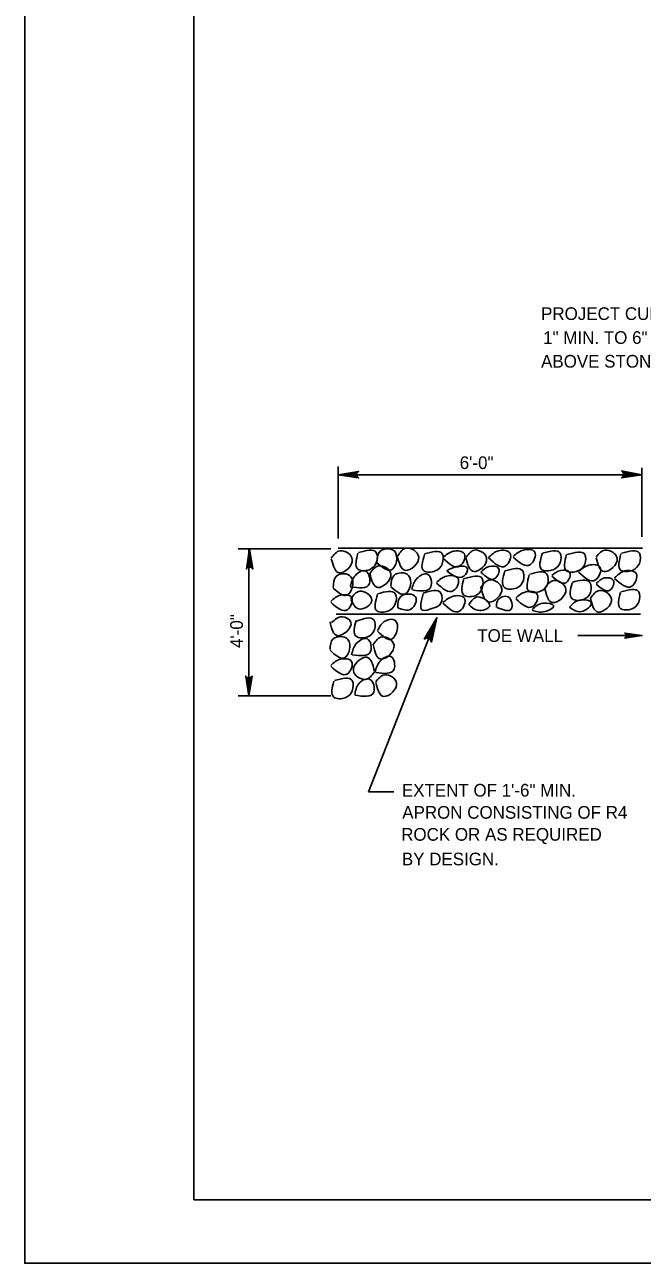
# Model space of a CAD drawing. Extents: x 639011 to 639866, y 298840 to 300028.
# Drawn here: x 639011.3 to 639157.4, y 298839.8 to 299133.1 of the extents above; entities that cross this region are included whole.
import ezdxf

# ---------------------------------------------------------------- set-up
doc = ezdxf.new("R2010")
doc.units = 0
doc.layers.add('2', color=7, linetype='Continuous')
doc.layers.add('PLT-BNDY', color=7, linetype='Continuous')

msp = doc.modelspace()

# ---------------------------------------------------------------- linework, layer by layer
at = {"layer": '2'}
for p, q in [((639051.26, 298854.83), (639051.26, 299418.83)), ((639085.44, 299011.4), (639085.44, 299028.5)), ((639157.29, 299011.85), (639157.29, 299028.2)), ((639085.44, 299026.55), (639157.29, 299026.55)), ((639061.74, 299009), (639083.64, 299009)), ((639064.29, 298974.2), (639064.29, 299008.85)), ((639085.44, 299009.15), (639157.44, 299009.15)), ((639084.98, 298993.53), (639156.98, 298993.53)), ((639108.79, 298992.68), (639092.56, 298951.49)), ((639142.14, 298988.45), (639157.29, 298988.45)), ((639061.74, 298974.2), (639083.64, 298974.2)), ((639092.56, 298951.49), (639098.56, 298951.49)), ((639837.26, 298854.83), (639051.26, 298854.83))]:
    msp.add_line(p, q, dxfattribs=at)
for points in [[(639089.94, 299026.1), (639089.79, 299026.4), (639085.44, 299026.55), (639089.94, 299026.1), (639090.24, 299025.8), (639085.44, 299026.55), (639089.79, 299026.85), (639089.94, 299027.15), (639085.44, 299026.55), (639090.24, 299027.3), (639089.94, 299027.15)], [(639152.79, 299027.15), (639152.94, 299026.85), (639157.29, 299026.55), (639152.79, 299027.15), (639152.49, 299027.45), (639157.29, 299026.55), (639152.94, 299026.4), (639152.79, 299026.1), (639157.29, 299026.55), (639152.49, 299025.8), (639152.79, 299026.1)], [(639063.84, 299004.5), (639064.14, 299004.65), (639064.44, 299009), (639063.84, 299004.5), (639063.69, 299004.2), (639064.44, 299009), (639064.59, 299004.65), (639065.04, 299004.5), (639064.44, 299009), (639065.19, 299004.2), (639065.04, 299004.5)], [(639106.11, 298987.78), (639106.56, 298987.83), (639108.79, 298992.68), (639106.11, 298987.78), (639105.78, 298987.61), (639108.79, 298992.68), (639107.08, 298987.63), (639107.38, 298987.3), (639108.79, 298992.68), (639107.51, 298986.92), (639107.38, 298987.3)], [(639153.39, 298988.9), (639153.54, 298988.6), (639157.29, 298988.45), (639153.39, 298988.9), (639153.24, 298989.05), (639157.29, 298988.45), (639153.54, 298988.3), (639153.39, 298988), (639157.29, 298988.45), (639153.24, 298987.85), (639153.39, 298988)], [(639064.89, 298978.7), (639064.44, 298978.4), (639064.29, 298974.2), (639064.89, 298978.7), (639065.04, 298978.85), (639064.29, 298974.2), (639063.99, 298978.4), (639063.69, 298978.7), (639064.29, 298974.2), (639063.54, 298978.85), (639063.69, 298978.7)]]:
    msp.add_lwpolyline(points, dxfattribs=at)
for points in [[(639083.79, 299006.75), (639085.89, 299008.55), (639088.74, 299006.45), (639085.74, 299003.3), (639083.79, 299006.6)], [(639090.24, 299008.1), (639094.44, 299008.1), (639094.44, 299005.7), (639092.79, 299004.05), (639090.09, 299004.2), (639090.09, 299007.95)], [(639094.59, 299005.85), (639095.34, 299008.4), (639098.79, 299008.4), (639098.04, 299004.05), (639094.59, 299005.7)], [(639099.54, 299007.35), (639101.49, 299009.15), (639104.49, 299007.05), (639101.34, 299003.9), (639099.39, 299007.35)], [(639105.84, 299007.8), (639110.04, 299007.8), (639110.04, 299005.4), (639108.39, 299003.75), (639105.69, 299003.75), (639105.84, 299007.65)], [(639110.19, 299006.9), (639112.59, 299008.4), (639115.29, 299007.8), (639114.24, 299004.95), (639110.19, 299006.75)], [(639115.74, 299007.05), (639117.69, 299008.7), (639120.54, 299006.75), (639117.54, 299003.6), (639115.59, 299006.9)], [(639120.99, 299006.9), (639123.39, 299008.55), (639126.09, 299007.95), (639125.04, 299004.95), (639120.99, 299006.9)], [(639126.84, 299007.2), (639129.24, 299008.7), (639131.94, 299008.25), (639130.89, 299005.25), (639126.84, 299007.05)], [(639133.74, 299007.95), (639137.94, 299007.95), (639137.94, 299005.7), (639136.29, 299004.05), (639133.59, 299004.05), (639133.74, 299007.95)], [(639139.59, 299007.65), (639143.79, 299007.65), (639143.79, 299005.4), (639142.14, 299003.75), (639139.44, 299003.75), (639139.44, 299007.65)], [(639146.49, 299007.05), (639148.59, 299008.7), (639151.44, 299006.75), (639148.29, 299003.6), (639146.49, 299006.9)], [(639152.49, 299007.95), (639156.69, 299007.95), (639156.69, 299005.55), (639155.04, 299003.9), (639152.34, 299003.9), (639152.34, 299007.8)], [(639088.29, 299000.15), (639089.49, 299002.7), (639091.89, 299003.75), (639092.79, 299000.75), (639088.29, 299000)], [(639092.94, 299003.15), (639095.04, 299004.95), (639097.89, 299003), (639094.74, 298999.85), (639092.94, 299003.15)], [(639111.09, 299003.75), (639113.49, 299004.8), (639116.04, 299004.35), (639115.14, 299002.55), (639111.09, 299003.75)], [(639119.19, 299003.45), (639121.14, 299004.8), (639123.39, 299004.35), (639122.49, 299001.95), (639119.19, 299003.45)], [(639124.89, 299003.75), (639129.09, 299003.75), (639129.24, 299001.5), (639127.59, 298999.7), (639124.74, 298999.85), (639124.89, 299003.75)], [(639130.74, 299003), (639134.79, 299003), (639134.94, 299000.6), (639133.29, 298998.95), (639130.59, 298998.95), (639130.59, 299002.85)], [(639135.99, 299002.7), (639138.09, 299003.9), (639140.19, 299003.45), (639139.44, 299001.05), (639135.99, 299002.55)], [(639142.29, 299003.6), (639144.69, 299005.1), (639147.39, 299004.65), (639146.34, 299001.65), (639142.29, 299003.45)], [(639150.84, 299002.1), (639153.24, 299003.75), (639155.94, 299003.15), (639154.89, 299000.15), (639150.84, 299001.95)], [(639084.24, 298999.85), (639084.99, 299002.55), (639088.44, 299002.4), (639087.54, 298998.05), (639084.24, 298999.7)], [(639097.89, 299000.15), (639098.64, 299002.7), (639102.09, 299002.7), (639101.34, 298998.35), (639097.89, 299000)], [(639102.84, 298999.4), (639104.04, 299001.95), (639106.59, 299003), (639107.34, 299000), (639102.99, 298999.25)], [(639108.69, 299001.05), (639111.09, 299002.55), (639113.79, 299001.95), (639112.74, 298999.1), (639108.69, 299000.9)], [(639115.29, 299001.95), (639119.49, 299001.95), (639119.49, 298999.7), (639117.84, 298997.9), (639115.14, 298998.05), (639115.14, 299001.95)], [(639119.19, 298999.85), (639121.29, 299001.65), (639124.14, 298999.55), (639121.14, 298996.4), (639119.19, 298999.85)], [(639134.34, 298999.7), (639136.44, 299001.5), (639139.29, 298999.4), (639136.14, 298996.25), (639134.34, 298999.55)], [(639140.79, 299001.05), (639144.99, 299001.05), (639145.14, 298998.65), (639143.49, 298997), (639140.79, 298997.15), (639140.79, 299000.9)], [(639146.49, 299000.75), (639148.44, 299002.1), (639150.54, 299001.5), (639149.79, 298999.25), (639146.49, 299000.6)], [(639083.64, 298996.55), (639086.04, 298998.05), (639088.59, 298997.45), (639087.69, 298994.6), (639083.64, 298996.4)], [(639088.44, 298997.15), (639090.54, 298998.95), (639093.39, 298996.85), (639090.35, 298994.76), (639088.44, 298997)], [(639094.74, 298998.35), (639098.94, 298998.35), (639098.94, 298995.95), (639097.29, 298994.3), (639094.59, 298994.3), (639094.74, 298998.2)], [(639099.54, 298995.05), (639100.29, 298997.75), (639103.74, 298997.6), (639102.69, 298994.76), (639099.54, 298995.05)], [(639105.54, 298998.5), (639109.74, 298998.5), (639109.74, 298996.1), (639107.78, 298994.91), (639105.39, 298994.45), (639105.54, 298998.35)], [(639110.19, 298996.25), (639112.59, 298997.75), (639115.29, 298997.3), (639114.24, 298994.3), (639110.19, 298996.1)], [(639122.9, 298995.07), (639123.09, 298996.7), (639125.64, 298997.6), (639126.39, 298994.75), (639123.06, 298995.07)], [(639127.44, 298997.3), (639129.84, 298998.8), (639132.54, 298998.2), (639131.49, 298995.35), (639127.44, 298997.15)], [(639145.14, 298997.3), (639147.24, 298999.1), (639150.09, 298997.15), (639146.94, 298994), (639145.14, 298997.3)], [(639152.34, 298998.8), (639156.54, 298998.8), (639156.54, 298996.4), (639154.89, 298994.75), (639152.19, 298994.9), (639152.19, 298998.65)], [(639116.34, 298995.8), (639118.44, 298997.6), (639121.29, 298995.5), (639118.43, 298994.45), (639116.34, 298995.8)], [(639131.34, 298994.6), (639133.89, 298996.1), (639136.44, 298995.5), (639134.32, 298994.14), (639131.34, 298994.45)], [(639140.19, 298995.2), (639142.59, 298996.85), (639145.29, 298996.25), (639142.96, 298994.14), (639140.19, 298995.2)], [(639083.87, 298991.52), (639086.34, 298992.91), (639088.44, 298991.58), (639085.29, 298988.43), (639083.49, 298991.73)], [(639089.73, 298991.83), (639093.84, 298992.18), (639093.99, 298989.78), (639092.34, 298988.13), (639089.64, 298988.28), (639089.64, 298992.03)], [(639094.74, 298989.63), (639096.68, 298991.98), (639098.94, 298992.03), (639098.19, 298987.68), (639094.74, 298989.48)], [(639083.49, 298985.13), (639084.24, 298987.68), (639087.69, 298987.53), (639086.94, 298983.18), (639083.49, 298984.98)], [(639088.59, 298983.93), (639089.79, 298986.63), (639092.34, 298987.68), (639093.09, 298984.68), (639088.74, 298983.93)], [(639093.69, 298986.33), (639095.79, 298988.13), (639098.64, 298986.18), (639095.49, 298982.88), (639093.69, 298986.33)], [(639083.64, 298981.38), (639086.04, 298982.88), (639088.59, 298982.28), (639087.69, 298979.43), (639083.64, 298981.23)], [(639093.99, 298979.88), (639091.89, 298978.08), (639089.04, 298980.18), (639092.19, 298983.33), (639093.99, 298980.03)], [(639094.14, 298979.73), (639095.34, 298982.43), (639097.89, 298983.48), (639098.64, 298980.48), (639094.29, 298979.73)], [(639084.54, 298977.78), (639088.74, 298977.78), (639088.74, 298975.38), (639087.09, 298973.73), (639084.39, 298973.88), (639084.39, 298977.63)], [(639089.34, 298974.48), (639090.39, 298977.18), (639092.94, 298978.08), (639093.84, 298975.08), (639089.34, 298974.33)], [(639094.29, 298977.48), (639096.39, 298979.13), (639099.24, 298977.18), (639096.24, 298974.03), (639094.29, 298977.33)]]:
    msp.add_spline(points, degree=3, dxfattribs=at)
at = {"layer": 'PLT-BNDY'}
msp.add_lwpolyline([(639011.26, 299433.83), (639852.26, 299433.83), (639852.26, 298839.83), (639011.26, 298839.83)], close=True, dxfattribs=at)

# ---------------------------------------------------------------- texts
at = {"layer": '2'}
for s, height, p in [('PROJECT CULVERT END ', 2.9999, (639133.43, 299063.18)), ('1" MIN. TO 6" MAX.', 2.9999, (639133.93, 299057.52)), ('ABOVE STONE SLOPE WALL.', 2.9999, (639133.43, 299051.9)), ('6\'-0"', 3, (639114.18, 299027.89)), ('TOE WALL', 3, (639118.33, 298986.95)), ('EXTENT OF 1\'-6" MIN.', 2.9999, (639100.49, 298950.33)), ('APRON CONSISTING OF R4', 2.9999, (639100.58, 298945.09)), ('ROCK OR AS REQUIRED', 2.9999, (639100.33, 298939.88)), ('BY DESIGN.', 3, (639100.49, 298934.05))]:
    msp.add_text(s, height=height, dxfattribs=at).set_placement(p)
msp.add_text('4\'-0"', height=3, rotation=90, dxfattribs=at).set_placement((639062.86, 298985.52))

doc.saveas('drawing.dxf')
